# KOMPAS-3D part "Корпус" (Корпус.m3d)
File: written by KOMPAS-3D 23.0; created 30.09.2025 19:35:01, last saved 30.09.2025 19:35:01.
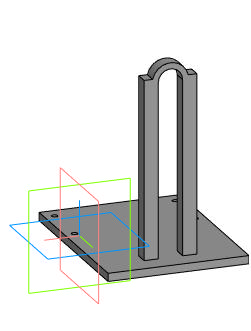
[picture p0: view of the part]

Document properties: Автор: Inspektor_Kot; Полное имя файла: I:\Autodesk Inventor Projects\ИМ-ИТ ЦД\Вариант 6\Корпус.m3d

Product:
- Part/product: Корпус

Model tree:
1. Эскиз:1  (with: Операция без истории:1)  (labels: I:\Autodesk Inventor Projects\ИМ-ИТ ЦД\Вариант 6\Шатун.a3d)
2. Элемент выдавливания:1
     Расстояние 1 = 4
3. Эскиз:2  (with: Элемент выдавливания:1, Элемент выдавливания:2)  (labels: I:\Autodesk Inventor Projects\ИМ-ИТ ЦД\Вариант 6\Шатун.a3d)
4. Элемент выдавливания:2
     Расстояние 1 = 86
5. Эскиз:4  (with: Элемент выдавливания:2)
6. Элемент выдавливания:3  (with: Элемент выдавливания:2)
     Расстояние 1 = -7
